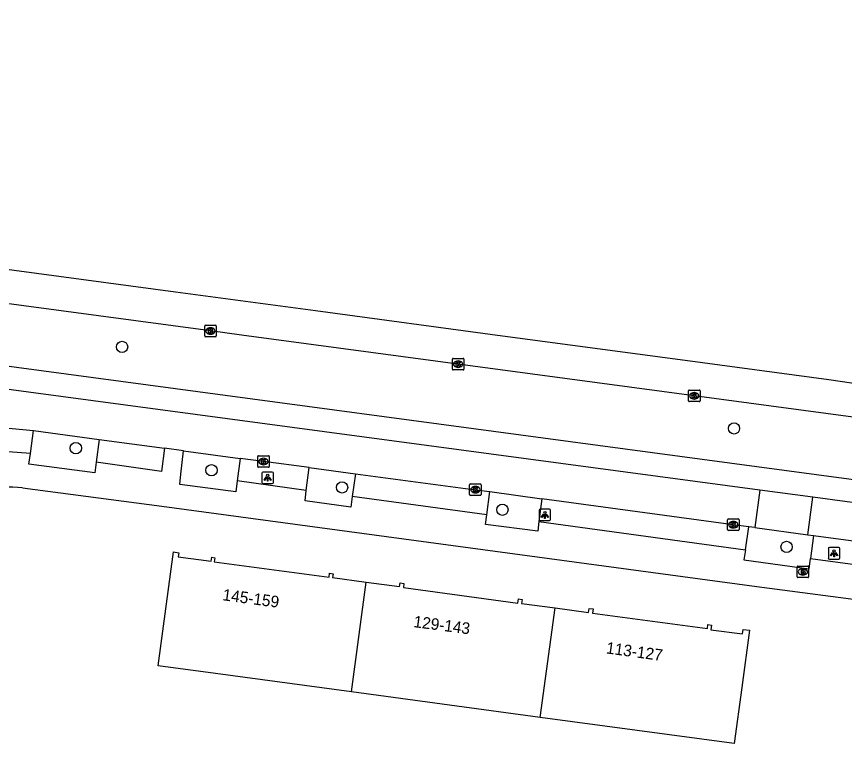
# Model space of a CAD drawing. Extents: x 161258 to 161838, y 380836 to 381727.
# Drawn here: x 161598.7 to 161670.2, y 381638.9 to 381701.8 of the extents above; entities that cross this region are included whole.
import ezdxf

# ---------------------------------------------------------------- set-up
doc = ezdxf.new("R2010")
doc.units = 0
for name, color, linetype in [('IMGEO_Boom', 7, 'Continuous'), ('IMGEO_Brandkraan', 7, 'Continuous'), ('IMGEO_Kolk', 7, 'Continuous'), ('IMGEO_Lichtpunt', 7, 'Continuous'), ('IMGEO_Pand', 7, 'Continuous'), ('IMGEO_Pand_nummerreeks', 7, 'Continuous'), ('IMGEO_Parkeervlak_halfverhard', 7, 'Continuous'), ('IMGEO_Parkeervlak_open', 7, 'Continuous'), ('IMGEO_Rijbaan_lokaal_open', 7, 'Continuous'), ('IMGEO_Rijbaan_regionaal_gesloten', 7, 'Continuous'), ('IMGEO_Voetpad_open', 7, 'Continuous')]:
    doc.layers.add(name, color=color, linetype=linetype)

msp = doc.modelspace()

# ---------------------------------------------------------------- linework, layer by layer
at = {"layer": 'IMGEO_Boom'}
for centre in [(161607.811, 381673.217), (161660.703, 381666.175), (161603.814, 381664.459), (161615.541, 381662.553), (161626.823, 381661.069), (161640.685, 381659.137), (161665.253, 381655.923)]:
    msp.add_circle(centre, 0.489, dxfattribs=at)
at = {"layer": 'IMGEO_Brandkraan'}
for p, q in [((161666.155, 381653.343), (161666.155, 381654.195)), ((161666.23, 381654.269), (161667.082, 381654.269)), ((161666.643, 381654.049), (161666.668, 381654.049)), ((161667.156, 381654.195), (161667.156, 381653.343)), ((161666.666, 381653.489), (161666.641, 381653.489)), ((161667.082, 381653.269), (161666.23, 381653.269))]:
    msp.add_line(p, q, dxfattribs=at)
for points in [[(161666.155, 381653.343), (161666.155, 381654.195)], [(161666.23, 381654.269), (161667.082, 381654.269)], [(161667.156, 381654.195), (161667.156, 381653.343)], [(161666.503, 381653.969), (161666.503, 381653.569), (161666.716, 381653.569)], [(161666.734, 381653.969), (161666.503, 381653.969)], [(161666.682, 381653.888), (161666.628, 381653.888), (161666.628, 381653.812)], [(161666.628, 381653.812), (161666.681, 381653.812)], [(161666.69, 381653.736), (161666.628, 381653.736), (161666.628, 381653.655)], [(161666.628, 381653.655), (161666.69, 381653.655)], [(161667.082, 381653.269), (161666.23, 381653.269)]]:
    msp.add_lwpolyline(points, dxfattribs=at)
for centre, radius, start, end in [((161666.232, 381654.193), 0.0765, 91.55205, 178.44795), ((161666.232, 381654.193), 0.0765, 91.55205, 178.44795), ((161667.08, 381654.193), 0.0765, 1.55205, 88.44795), ((161667.08, 381654.193), 0.0765, 1.55205, 88.44795), ((161666.232, 381653.345), 0.0765, 181.55205, 268.44795), ((161666.232, 381653.345), 0.0765, 181.55205, 268.44795), ((161666.683, 381653.85), 0.0379, 267.82845, 90.93552), ((161666.691, 381653.695), 0.0404, 269.87594, 90.50774), ((161666.722, 381653.82), 0.251, 268.66757, 293.53466), ((161666.738, 381653.824), 0.145, 59.4692, 91.53667), ((161666.763, 381653.871), 0.0922, 285.51372, 58.15012), ((161666.768, 381653.679), 0.105, 301.31148, 78.98903), ((161667.08, 381653.345), 0.0765, 271.55205, 358.44795), ((161667.08, 381653.345), 0.0765, 271.55205, 358.44795)]:
    msp.add_arc(centre, radius, start, end, dxfattribs=at)
for centre, major_axis, ratio, start_param, end_param in [((161666.642, 381653.769), (-0.387, 0.002), 0.722429, 4.712389, 7.853982), ((161666.667, 381653.769), (-0.39, 0.002), 0.717154, 1.570796, 4.712389)]:
    msp.add_ellipse(centre, major_axis=major_axis, ratio=ratio, start_param=start_param, end_param=end_param, dxfattribs=at)
at = {"layer": 'IMGEO_Kolk'}
for p, q in [((161614.95, 381674.17), (161614.95, 381675.022)), ((161615.025, 381675.096), (161615.877, 381675.096)), ((161615.438, 381674.876), (161615.463, 381674.876)), ((161615.951, 381675.022), (161615.951, 381674.17)), ((161615.877, 381674.096), (161615.025, 381674.096)), ((161615.461, 381674.316), (161615.436, 381674.316)), ((161636.358, 381671.299), (161636.358, 381672.151)), ((161636.433, 381672.225), (161637.285, 381672.225)), ((161636.846, 381672.005), (161636.871, 381672.005)), ((161637.359, 381672.151), (161637.359, 381671.299)), ((161637.285, 381671.225), (161636.433, 381671.225)), ((161636.869, 381671.445), (161636.844, 381671.445)), ((161656.765, 381668.561), (161656.765, 381669.413)), ((161656.84, 381669.487), (161657.692, 381669.487)), ((161657.253, 381669.267), (161657.278, 381669.267)), ((161657.766, 381669.413), (161657.766, 381668.561)), ((161657.692, 381668.487), (161656.84, 381668.487)), ((161657.276, 381668.707), (161657.251, 381668.707)), ((161619.532, 381662.884), (161619.532, 381663.736)), ((161619.607, 381663.81), (161620.459, 381663.81)), ((161620.02, 381663.59), (161620.045, 381663.59)), ((161620.533, 381663.736), (161620.533, 381662.884)), ((161620.459, 381662.81), (161619.607, 381662.81)), ((161620.043, 381663.03), (161620.018, 381663.03)), ((161637.851, 381660.446), (161637.851, 381661.298)), ((161637.926, 381661.372), (161638.778, 381661.372)), ((161638.852, 381661.298), (161638.852, 381660.446)), ((161638.362, 381660.592), (161638.337, 381660.592)), ((161638.339, 381661.152), (161638.364, 381661.152)), ((161638.778, 381660.372), (161637.926, 381660.372)), ((161660.218, 381658.343), (161661.07, 381658.343)), ((161660.143, 381657.417), (161660.143, 381658.269)), ((161660.631, 381658.123), (161660.656, 381658.123)), ((161661.144, 381658.269), (161661.144, 381657.417)), ((161661.07, 381657.343), (161660.218, 381657.343)), ((161660.654, 381657.563), (161660.629, 381657.563))]:
    msp.add_line(p, q, dxfattribs=at)
for points in [[(161614.95, 381674.17), (161614.95, 381675.022)], [(161615.025, 381675.096), (161615.877, 381675.096)], [(161615.951, 381675.022), (161615.951, 381674.17)], [(161615.877, 381674.096), (161615.025, 381674.096)], [(161615.271, 381674.796), (161615.394, 381674.796), (161615.394, 381674.645), (161615.524, 381674.796), (161615.688, 381674.796), (161615.542, 381674.645), (161615.695, 381674.396), (161615.543, 381674.396), (161615.458, 381674.56), (161615.394, 381674.493), (161615.394, 381674.396), (161615.271, 381674.396), (161615.271, 381674.796)], [(161636.358, 381671.299), (161636.358, 381672.151)], [(161636.433, 381672.225), (161637.285, 381672.225)], [(161637.359, 381672.151), (161637.359, 381671.299)], [(161637.285, 381671.225), (161636.433, 381671.225)], [(161636.679, 381671.925), (161636.802, 381671.925), (161636.802, 381671.774), (161636.932, 381671.925), (161637.096, 381671.925), (161636.95, 381671.774), (161637.103, 381671.525), (161636.951, 381671.525), (161636.866, 381671.689), (161636.802, 381671.622), (161636.802, 381671.525), (161636.679, 381671.525), (161636.679, 381671.925)], [(161656.765, 381668.561), (161656.765, 381669.413)], [(161656.84, 381669.487), (161657.692, 381669.487)], [(161657.086, 381669.187), (161657.209, 381669.187), (161657.209, 381669.036), (161657.339, 381669.187), (161657.503, 381669.187), (161657.357, 381669.036), (161657.51, 381668.787), (161657.358, 381668.787), (161657.273, 381668.951), (161657.209, 381668.884), (161657.209, 381668.787), (161657.086, 381668.787), (161657.086, 381669.187)], [(161657.766, 381669.413), (161657.766, 381668.561)], [(161657.692, 381668.487), (161656.84, 381668.487)], [(161619.532, 381662.884), (161619.532, 381663.736)], [(161619.607, 381663.81), (161620.459, 381663.81)], [(161619.853, 381663.51), (161619.976, 381663.51), (161619.976, 381663.359), (161620.106, 381663.51), (161620.27, 381663.51), (161620.124, 381663.359), (161620.277, 381663.11), (161620.125, 381663.11), (161620.04, 381663.274), (161619.976, 381663.207), (161619.976, 381663.11), (161619.853, 381663.11), (161619.853, 381663.51)], [(161620.533, 381663.736), (161620.533, 381662.884)], [(161620.459, 381662.81), (161619.607, 381662.81)], [(161637.851, 381660.446), (161637.851, 381661.298)], [(161637.926, 381661.372), (161638.778, 381661.372)], [(161638.852, 381661.298), (161638.852, 381660.446)], [(161638.172, 381661.072), (161638.295, 381661.072), (161638.295, 381660.921), (161638.425, 381661.072), (161638.589, 381661.072), (161638.443, 381660.921), (161638.596, 381660.672), (161638.444, 381660.672), (161638.359, 381660.836), (161638.295, 381660.769), (161638.295, 381660.672), (161638.172, 381660.672), (161638.172, 381661.072)], [(161638.778, 381660.372), (161637.926, 381660.372)], [(161660.218, 381658.343), (161661.07, 381658.343)], [(161660.143, 381657.417), (161660.143, 381658.269)], [(161660.464, 381658.043), (161660.587, 381658.043), (161660.587, 381657.892), (161660.717, 381658.043), (161660.881, 381658.043), (161660.735, 381657.892), (161660.888, 381657.643), (161660.736, 381657.643), (161660.651, 381657.807), (161660.587, 381657.74), (161660.587, 381657.643), (161660.464, 381657.643), (161660.464, 381658.043)], [(161661.144, 381658.269), (161661.144, 381657.417)], [(161661.07, 381657.343), (161660.218, 381657.343)]]:
    msp.add_lwpolyline(points, dxfattribs=at)
for centre, start, end in [((161615.027, 381675.02), 91.55205, 178.44795), ((161615.027, 381675.02), 91.55205, 178.44795), ((161615.875, 381675.02), 1.55205, 88.44795), ((161615.875, 381675.02), 1.55205, 88.44795), ((161615.027, 381674.172), 181.55205, 268.44795), ((161615.027, 381674.172), 181.55205, 268.44795), ((161615.875, 381674.172), 271.55205, 358.44795), ((161615.875, 381674.172), 271.55205, 358.44795), ((161636.435, 381672.149), 91.55205, 178.44795), ((161636.435, 381672.149), 91.55205, 178.44795), ((161637.283, 381672.149), 1.55205, 88.44795), ((161637.283, 381672.149), 1.55205, 88.44795), ((161636.435, 381671.301), 181.55205, 268.44795), ((161636.435, 381671.301), 181.55205, 268.44795), ((161637.283, 381671.301), 271.55205, 358.44795), ((161637.283, 381671.301), 271.55205, 358.44795), ((161656.842, 381669.411), 91.55205, 178.44795), ((161656.842, 381669.411), 91.55205, 178.44795), ((161657.69, 381669.411), 1.55205, 88.44795), ((161657.69, 381669.411), 1.55205, 88.44795), ((161656.842, 381668.563), 181.55205, 268.44795), ((161656.842, 381668.563), 181.55205, 268.44795), ((161657.69, 381668.563), 271.55205, 358.44795), ((161657.69, 381668.563), 271.55205, 358.44795), ((161619.609, 381663.734), 91.55205, 178.44795), ((161619.609, 381663.734), 91.55205, 178.44795), ((161620.457, 381663.734), 1.55205, 88.44795), ((161620.457, 381663.734), 1.55205, 88.44795), ((161619.609, 381662.886), 181.55205, 268.44795), ((161619.609, 381662.886), 181.55205, 268.44795), ((161620.457, 381662.886), 271.55205, 358.44795), ((161620.457, 381662.886), 271.55205, 358.44795), ((161637.928, 381661.296), 91.55205, 178.44795), ((161637.928, 381661.296), 91.55205, 178.44795), ((161638.776, 381661.296), 1.55205, 88.44795), ((161638.776, 381661.296), 1.55205, 88.44795), ((161637.928, 381660.448), 181.55205, 268.44795), ((161637.928, 381660.448), 181.55205, 268.44795), ((161638.776, 381660.448), 271.55205, 358.44795), ((161638.776, 381660.448), 271.55205, 358.44795), ((161660.22, 381658.267), 91.55205, 178.44795), ((161660.22, 381658.267), 91.55205, 178.44795), ((161661.068, 381658.267), 1.55205, 88.44795), ((161661.068, 381658.267), 1.55205, 88.44795), ((161660.22, 381657.419), 181.55205, 268.44795), ((161660.22, 381657.419), 181.55205, 268.44795), ((161661.068, 381657.419), 271.55205, 358.44795), ((161661.068, 381657.419), 271.55205, 358.44795)]:
    msp.add_arc(centre, 0.0765, start, end, dxfattribs=at)
for centre, major_axis, ratio, start_param, end_param in [((161615.437, 381674.596), (-0.387, 0.002), 0.722429, 4.712389, 7.853982), ((161615.462, 381674.596), (-0.39, 0.002), 0.717154, 1.570796, 4.712389), ((161636.845, 381671.725), (-0.387, 0.002), 0.722429, 4.712389, 7.853982), ((161636.87, 381671.725), (-0.39, 0.002), 0.717154, 1.570796, 4.712389), ((161657.252, 381668.987), (-0.387, 0.002), 0.722429, 4.712389, 7.853982), ((161657.277, 381668.987), (-0.39, 0.002), 0.717154, 1.570796, 4.712389), ((161620.019, 381663.31), (-0.387, 0.002), 0.722429, 4.712389, 7.853982), ((161620.044, 381663.31), (-0.39, 0.002), 0.717154, 1.570796, 4.712389), ((161638.338, 381660.872), (-0.387, 0.002), 0.722429, 4.712389, 7.853982), ((161638.363, 381660.872), (-0.39, 0.002), 0.717154, 1.570796, 4.712389), ((161660.63, 381657.843), (-0.387, 0.002), 0.722429, 4.712389, 7.853982), ((161660.655, 381657.843), (-0.39, 0.002), 0.717154, 1.570796, 4.712389)]:
    msp.add_ellipse(centre, major_axis=major_axis, ratio=ratio, start_param=start_param, end_param=end_param, dxfattribs=at)
at = {"layer": 'IMGEO_Lichtpunt'}
for p, q in [((161619.895, 381662.305), (161619.895, 381661.498)), ((161619.895, 381662.305), (161619.895, 381661.498)), ((161620.797, 381662.4), (161619.989, 381662.4)), ((161620.797, 381662.4), (161619.989, 381662.4)), ((161620.891, 381661.498), (161620.891, 381662.305)), ((161620.891, 381661.498), (161620.891, 381662.305)), ((161619.989, 381661.404), (161620.797, 381661.404)), ((161619.989, 381661.404), (161620.797, 381661.404)), ((161643.856, 381659.1), (161643.856, 381658.293)), ((161643.856, 381659.1), (161643.856, 381658.293)), ((161644.758, 381659.195), (161643.95, 381659.195)), ((161644.758, 381659.195), (161643.95, 381659.195)), ((161644.852, 381658.293), (161644.852, 381659.1)), ((161644.852, 381658.293), (161644.852, 381659.1)), ((161643.95, 381658.199), (161644.758, 381658.199)), ((161643.95, 381658.199), (161644.758, 381658.199)), ((161668.857, 381655.776), (161668.857, 381654.969)), ((161668.857, 381655.776), (161668.857, 381654.969)), ((161669.759, 381655.871), (161668.951, 381655.871)), ((161669.759, 381655.871), (161668.951, 381655.871)), ((161669.853, 381654.969), (161669.853, 381655.776)), ((161669.853, 381654.969), (161669.853, 381655.776)), ((161668.951, 381654.875), (161669.759, 381654.875)), ((161668.951, 381654.875), (161669.759, 381654.875))]:
    msp.add_line(p, q, dxfattribs=at)
for points in [[(161620.269, 381661.969), (161620.308, 381661.941), (161620.12, 381661.679), (161620.082, 381661.706), (161620.269, 381661.969)], [(161620.371, 381661.921), (161620.418, 381661.921), (161620.418, 381661.599), (161620.371, 381661.599), (161620.371, 381661.921)], [(161620.481, 381661.941), (161620.519, 381661.968), (161620.706, 381661.706), (161620.667, 381661.678), (161620.481, 381661.941)], [(161644.23, 381658.764), (161644.269, 381658.736), (161644.081, 381658.474), (161644.043, 381658.501), (161644.23, 381658.764)], [(161644.332, 381658.716), (161644.379, 381658.716), (161644.379, 381658.394), (161644.332, 381658.394), (161644.332, 381658.716)], [(161644.442, 381658.736), (161644.48, 381658.763), (161644.667, 381658.501), (161644.628, 381658.473), (161644.442, 381658.736)], [(161669.231, 381655.44), (161669.27, 381655.412), (161669.082, 381655.15), (161669.044, 381655.177), (161669.231, 381655.44)], [(161669.333, 381655.392), (161669.38, 381655.392), (161669.38, 381655.07), (161669.333, 381655.07), (161669.333, 381655.392)], [(161669.443, 381655.412), (161669.481, 381655.439), (161669.668, 381655.177), (161669.629, 381655.149), (161669.443, 381655.412)]]:
    msp.add_lwpolyline(points, dxfattribs=at)
for centre in [(161620.394, 381662.103), (161644.355, 381658.898), (161669.356, 381655.574)]:
    msp.add_circle(centre, 0.0994, dxfattribs=at)
for centre, start, end in [((161619.989, 381662.305), 90, 180), ((161619.989, 381662.305), 90, 180), ((161620.797, 381662.305), 0, 90), ((161620.797, 381662.305), 0, 90), ((161619.989, 381661.498), 180, 270), ((161619.989, 381661.498), 180, 270), ((161620.797, 381661.498), 270, 0), ((161620.797, 381661.498), 270, 360), ((161643.95, 381659.1), 90, 180), ((161643.95, 381659.1), 90, 180), ((161644.758, 381659.1), 0, 90), ((161644.758, 381659.1), 0, 90), ((161643.95, 381658.293), 180, 270), ((161643.95, 381658.293), 180, 270), ((161644.758, 381658.293), 270, 0), ((161644.758, 381658.293), 270, 360), ((161668.951, 381655.776), 90, 180), ((161668.951, 381655.776), 90, 180), ((161669.759, 381655.776), 0, 90), ((161669.759, 381655.776), 0, 90), ((161668.951, 381654.969), 180, 270), ((161668.951, 381654.969), 180, 270), ((161669.759, 381654.969), 270, 0), ((161669.759, 381654.969), 270, 360)]:
    msp.add_arc(centre, 0.0946, start, end, dxfattribs=at)
at = {"layer": 'IMGEO_Pand'}
for points in [[(161627.626, 381643.385), (161615.892, 381644.965), (161610.936, 381645.632), (161612.263, 381655.486), (161612.719, 381655.424), (161612.672, 381655.072), (161615.508, 381654.69), (161615.554, 381655.027), (161615.829, 381654.99), (161615.782, 381654.645), (161625.697, 381653.309), (161625.742, 381653.644), (161626.056, 381653.602), (161626.011, 381653.266), (161628.905, 381652.876)], [(161627.626, 381643.385), (161628.905, 381652.876)], [(161628.905, 381652.876), (161631.798, 381652.487), (161631.843, 381652.817), (161632.176, 381652.772), (161632.126, 381652.403), (161642.024, 381651.07), (161642.072, 381651.429), (161642.386, 381651.387), (161642.339, 381651.04), (161645.237, 381650.649)], [(161645.237, 381650.649), (161648.134, 381650.259), (161648.181, 381650.609), (161648.533, 381650.562), (161648.485, 381650.206), (161658.399, 381648.87), (161658.444, 381649.202), (161658.753, 381649.16), (161658.7, 381648.764), (161661.437, 381648.395), (161661.491, 381648.794), (161662.041, 381648.72), (161661.374, 381643.765), (161660.722, 381638.927), (161643.962, 381641.184)], [(161643.962, 381641.184), (161645.237, 381650.649)], [(161643.962, 381641.184), (161627.626, 381643.385)]]:
    msp.add_lwpolyline(points, dxfattribs=at)
at = {"layer": 'IMGEO_Parkeervlak_halfverhard'}
msp.add_lwpolyline([(161591.581, 381672.404), (161665.053, 381662.56), (161687.397, 381659.556)], dxfattribs=at)
at = {"layer": 'IMGEO_Parkeervlak_open'}
for points in [[(161599.88, 381663.996), (161600.151, 381665.982)], [(161605.826, 381665.22), (161605.565, 381663.248)], [(161618.02, 381663.581), (161617.765, 381661.651)], [(161623.732, 381660.793), (161623.981, 381662.785)], [(161627.98, 381662.252), (161627.712, 381660.269)], [(161639.338, 381658.697), (161639.609, 381660.701)], [(161644.101, 381660.091), (161643.847, 381658.115)], [(161661.692, 381655.679), (161661.981, 381657.663)], [(161667.573, 381656.908), (161667.325, 381654.926)]]:
    msp.add_lwpolyline(points, dxfattribs=at)
at = {"layer": 'IMGEO_Rijbaan_lokaal_open'}
for points in [[(161662.932, 381660.822), (161590.884, 381670.486)], [(161596.114, 381666.375), (161600.151, 381665.982)], [(161600.151, 381665.982), (161605.826, 381665.22)], [(161605.826, 381665.22), (161611.485, 381664.459)], [(161613.107, 381664.241), (161611.485, 381664.459)], [(161613.107, 381664.241), (161618.02, 381663.581)], [(161623.981, 381662.785), (161620.033, 381663.31), (161618.02, 381663.581)], [(161623.981, 381662.785), (161627.98, 381662.252)], [(161627.98, 381662.252), (161638.352, 381660.872), (161639.609, 381660.701)], [(161639.609, 381660.701), (161644.101, 381660.091)], [(161662.932, 381660.822), (161662.493, 381657.593)], [(161667.513, 381660.211), (161662.932, 381660.822)], [(161661.981, 381657.663), (161660.644, 381657.843), (161644.101, 381660.091)], [(161667.085, 381656.974), (161667.513, 381660.211)], [(161687.091, 381657.568), (161667.513, 381660.211)], [(161662.493, 381657.593), (161661.981, 381657.663)], [(161662.493, 381657.593), (161667.085, 381656.974)], [(161667.085, 381656.974), (161667.573, 381656.908)], [(161667.573, 381656.908), (161674.685, 381655.948)]]:
    msp.add_lwpolyline(points, dxfattribs=at)
at = {"layer": 'IMGEO_Rijbaan_regionaal_gesloten'}
for points in [[(161679.007, 381666.04), (161677.666, 381666.255), (161657.266, 381668.988), (161618.127, 381674.239), (161615.451, 381674.598), (161596.053, 381677.191), (161575.643, 381679.932), (161555.208, 381682.652), (161534.802, 381685.416), (161514.402, 381688.138), (161500, 381690.051), (161493.724, 381690.885), (161474.493, 381693.446), (161433.673, 381698.93), (161413.286, 381701.641), (161412.199, 381701.786)], [(161503.684, 381692.551), (161519.925, 381690.409), (161544.014, 381687.173), (161560.228, 381684.995), (161572.343, 381683.367), (161592.223, 381680.696), (161612.423, 381677.982), (161624.53, 381676.356), (161640.688, 381674.185), (161656.473, 381672.064), (161668.901, 381670.395), (161680.859, 381668.646)]]:
    msp.add_lwpolyline(points, dxfattribs=at)
at = {"layer": 'IMGEO_Voetpad_open'}
for points in [[(161599.88, 381663.996), (161595.593, 381664.309)], [(161611.485, 381664.459), (161611.231, 381662.438), (161605.565, 381663.248)], [(161617.765, 381661.651), (161617.639, 381660.694), (161612.798, 381661.333), (161612.89, 381662.2), (161613.107, 381664.241)], [(161605.565, 381663.248), (161605.445, 381662.335), (161599.756, 381663.086), (161599.88, 381663.996)], [(161623.732, 381660.793), (161617.765, 381661.651)], [(161599.202, 381661.023), (161611.247, 381659.449), (161663.105, 381652.447), (161684.01, 381649.696), (161716.743, 381645.239), (161740.472, 381642.131), (161745.302, 381641.497)], [(161627.712, 381660.269), (161627.59, 381659.365), (161623.621, 381659.901), (161623.732, 381660.793)], [(161639.338, 381658.697), (161627.712, 381660.269)], [(161643.847, 381658.115), (161643.74, 381657.285), (161639.226, 381657.866), (161639.338, 381658.697)], [(161643.847, 381658.115), (161661.692, 381655.679)], [(161661.692, 381655.679), (161661.566, 381654.809), (161667.214, 381654.038), (161667.325, 381654.926)], [(161667.325, 381654.926), (161674.413, 381653.98)]]:
    msp.add_lwpolyline(points, dxfattribs=at)
msp.add_arc((161597.923, 381648.903), 12.188, 83.97509, 99.73009, dxfattribs=at)

# ---------------------------------------------------------------- texts
at = {"layer": 'IMGEO_Pand_nummerreeks'}
for s, rotation, p in [('145-159', 352.26198, (161616.453, 381651.316)), ('129-143', 352.56859, (161632.957, 381648.992)), ('113-127', 352.19169, (161649.604, 381646.722))]:
    msp.add_text(s, height=1, rotation=rotation, dxfattribs=at).set_placement(p)

doc.saveas('drawing.dxf')
